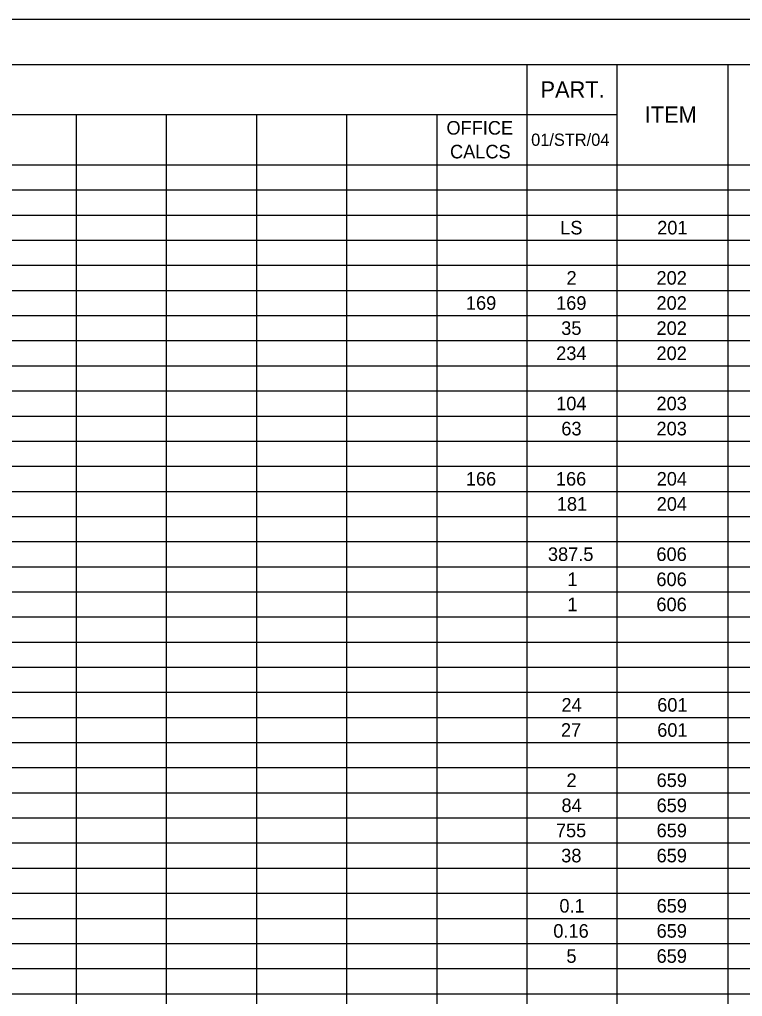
# Model space of a CAD drawing. Extents: x 0 to 34, y 0 to 22.
# Drawn here: x 8.91 to 16.96, y 11.11 to 22 of the extents above; entities that cross this region are included whole.
import ezdxf

# ---------------------------------------------------------------- set-up
doc = ezdxf.new("R2010")
doc.units = 0
for name, color, linetype in [('SH_Border', 7, 'Continuous'), ('SH_Cut_Line', 7, 'Continuous'), ('SH_Text', 7, 'Continuous')]:
    doc.layers.add(name, color=color, linetype=linetype)

msp = doc.modelspace()

# ---------------------------------------------------------------- linework, layer by layer
at = {"layer": 'SH_Border'}
msp.add_lwpolyline([(1.5, 21.5), (33.5, 21.5), (33.5, 0.5), (1.5, 0.5)], close=True, dxfattribs=at)
at = {"layer": 'SH_Cut_Line'}
msp.add_lwpolyline([(0, 0), (34, 0), (34, 22), (0, 22)], close=True, dxfattribs=at)
at = {"layer": 'SH_Text'}
for p, q in [((1.5, 21.5), (32, 21.5)), ((14.56, 21.5), (14.56, 0.5)), ((15.564, 21.5), (15.564, 0.5)), ((16.799, 21.5), (16.799, 0.5)), ((1.5, 20.94), (15.564, 20.94)), ((9.537, 20.94), (9.537, 0.5)), ((10.541, 20.94), (10.541, 0.5)), ((11.546, 20.94), (11.546, 0.5)), ((12.55, 20.94), (12.55, 0.5)), ((13.555, 20.94), (13.555, 0.5)), ((1.5, 20.38), (32, 20.38)), ((1.5, 20.1), (32, 20.1)), ((1.5, 19.82), (32, 19.82)), ((1.5, 19.54), (32, 19.54)), ((1.5, 19.26), (32, 19.26)), ((1.5, 18.98), (32, 18.98)), ((1.5, 18.7), (32, 18.7)), ((1.5, 18.42), (32, 18.42)), ((1.5, 18.14), (32, 18.14)), ((1.5, 17.86), (32, 17.86)), ((1.5, 17.58), (32, 17.58)), ((1.5, 17.3), (32, 17.3)), ((1.5, 17.02), (32, 17.02)), ((1.5, 16.74), (32, 16.74)), ((1.5, 16.46), (32, 16.46)), ((1.5, 16.18), (32, 16.18)), ((1.5, 15.9), (32, 15.9)), ((1.5, 15.62), (32, 15.62)), ((1.5, 15.34), (32, 15.34)), ((1.5, 15.06), (32, 15.06)), ((1.5, 14.78), (32, 14.78)), ((1.5, 14.5), (32, 14.5)), ((1.5, 14.22), (32, 14.22)), ((1.5, 13.94), (32, 13.94)), ((1.5, 13.66), (32, 13.66)), ((1.5, 13.38), (32, 13.38)), ((1.5, 13.1), (32, 13.1)), ((1.5, 12.82), (32, 12.82)), ((1.5, 12.54), (32, 12.54)), ((1.5, 12.26), (32, 12.26)), ((1.5, 11.98), (32, 11.98)), ((1.5, 11.7), (32, 11.7)), ((1.5, 11.42), (32, 11.42)), ((1.5, 11.14), (32, 11.14))]:
    msp.add_line(p, q, dxfattribs=at)

# ---------------------------------------------------------------- texts
for s, height, p in [('PART.', 0.1818, (14.712, 21.129)), ('ITEM', 0.1818, (15.873, 20.849)), ('OFFICE ', 0.1515, (13.664, 20.717)), ('01/STR/04', 0.1364, (14.608, 20.592)), ('CALCS', 0.1515, (13.704, 20.452)), ('LS', 0.1515, (14.932, 19.604)), ('201', 0.1515, (16.013, 19.604)), ('2', 0.152, (15.002, 19.044)), ('202', 0.1515, (16.005, 19.044)), ('169', 0.1515, (13.881, 18.764)), ('169', 0.1515, (14.886, 18.764)), ('202', 0.1515, (16.005, 18.764)), ('35', 0.1515, (14.943, 18.484)), ('202', 0.1515, (16.005, 18.484)), ('234', 0.1515, (14.887, 18.204)), ('202', 0.1515, (16.005, 18.204)), ('104', 0.1515, (14.887, 17.644)), ('203', 0.1515, (16.005, 17.644)), ('63', 0.1515, (14.944, 17.364)), ('203', 0.1515, (16.005, 17.364)), ('166', 0.1515, (13.88, 16.804)), ('166', 0.1515, (14.884, 16.804)), ('204', 0.1515, (16.007, 16.804)), ('181', 0.1515, (14.894, 16.524)), ('204', 0.1515, (16.007, 16.524)), ('387.5', 0.1515, (14.795, 15.964)), ('606', 0.1515, (16.004, 15.964)), ('1', 0.152, (15.011, 15.684)), ('606', 0.1515, (16.004, 15.684)), ('1', 0.152, (15.011, 15.404)), ('606', 0.1515, (16.004, 15.404)), ('24', 0.1515, (14.946, 14.284)), ('601', 0.1515, (16.013, 14.284)), ('27', 0.1515, (14.94, 14.004)), ('601', 0.1515, (16.013, 14.004)), ('2', 0.152, (15.002, 13.444)), ('659', 0.1515, (16.006, 13.444)), ('84', 0.1515, (14.946, 13.164)), ('659', 0.1515, (16.006, 13.164)), ('755', 0.1515, (14.884, 12.884)), ('659', 0.1515, (16.006, 12.884)), ('38', 0.1515, (14.943, 12.604)), ('659', 0.1515, (16.006, 12.604)), ('0.1', 0.1515, (14.923, 12.044)), ('659', 0.1515, (16.006, 12.044)), ('0.16', 0.1515, (14.855, 11.764)), ('659', 0.1515, (16.006, 11.764)), ('5', 0.152, (15.001, 11.484)), ('659', 0.1515, (16.006, 11.484))]:
    msp.add_text(s, height=height, dxfattribs=at).set_placement(p)

doc.saveas('drawing.dxf')
